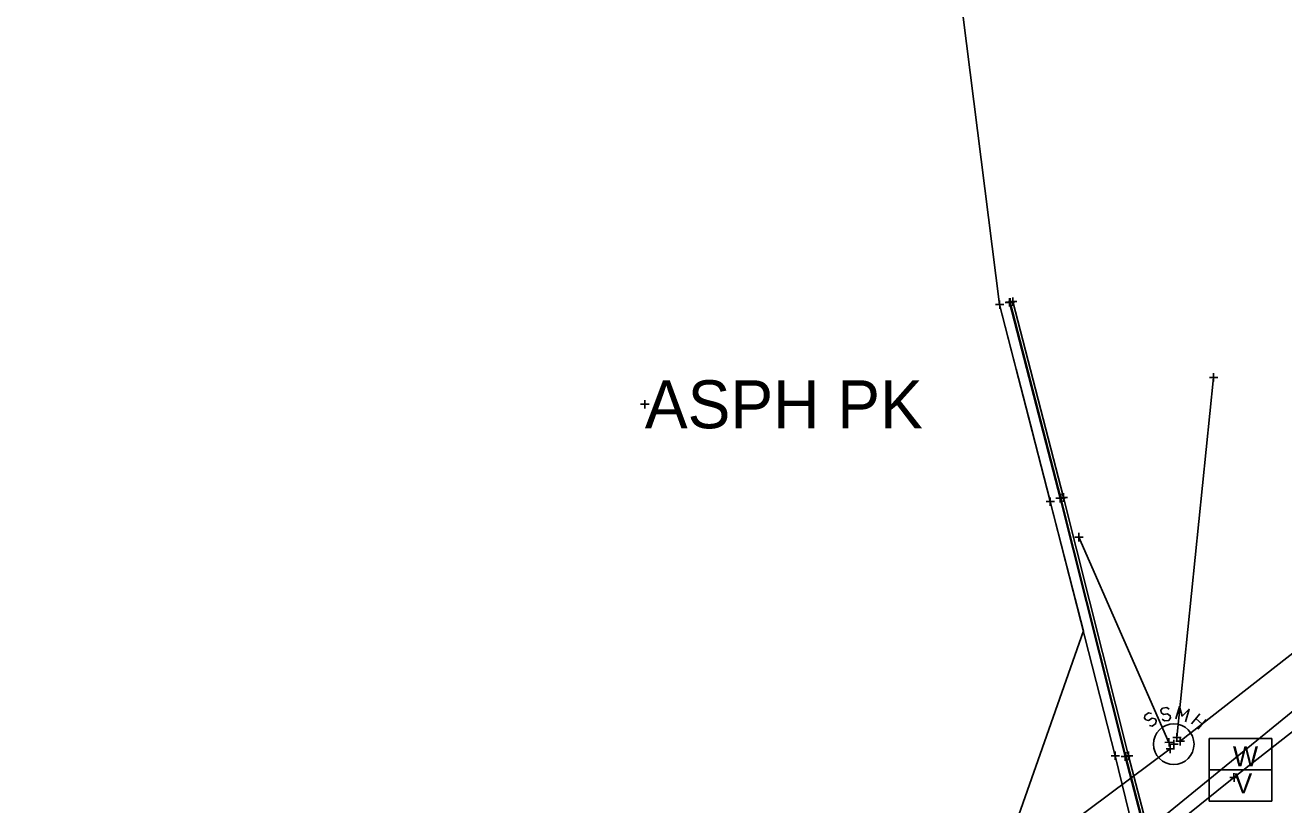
# Model space of a CAD drawing. Extents: x -1 to 1157254, y -1 to 2021979.
# Drawn here: x 1150044.1 to 1150233.1, y 2019619.2 to 2019736.2 of the extents above; entities that cross this region are included whole.
import ezdxf

# ---------------------------------------------------------------- set-up
doc = ezdxf.new("R2010")
doc.units = 0
for name, color, linetype in [('S_BUILDING_ANNOT', 7, 'Continuous'), ('S_CONTOUR_ANNOT', 7, 'Continuous'), ('S_CONTOUR_MINOR', 7, 'Continuous'), ('S_CTL_TABLE', 7, 'Continuous'), ('S_DROP_INLET', 7, 'Continuous'), ('S_EDGE_BITUMINOUS_ANNOT', 7, 'Continuous'), ('S_EDGE_PAVEMENT', 7, 'Continuous'), ('S_EDGE_PAVEMENT_ANNOT', 7, 'Continuous'), ('S_GAS_PUMP_ISLAND_ANNOT', 7, 'Continuous'), ('S_GATE', 7, 'Continuous')]:
    doc.layers.add(name, color=color, linetype=linetype)

msp = doc.modelspace()

# ---------------------------------------------------------------- linework, layer by layer
at = {"layer": 'S_BUILDING_ANNOT'}
for p, q in [((1150190.46, 2019693.61), (1150190.45, 2019694.88)), ((1150191.39, 2019694.6), (1150192.67, 2019694.6)), ((1150191.78, 2019694.7), (1150193.05, 2019694.7)), ((1150192.03, 2019693.96), (1150192.03, 2019695.23)), ((1150192.03, 2019694.6), (1150192.03, 2019694.6)), ((1150192.42, 2019694.06), (1150192.42, 2019695.33)), ((1150192.42, 2019694.7), (1150192.42, 2019694.7)), ((1150189.82, 2019694.25), (1150191.09, 2019694.25)), ((1150190.45, 2019694.25), (1150190.45, 2019694.25)), ((1150221.95, 2019683.31), (1150223.22, 2019683.32)), ((1150222.59, 2019682.68), (1150222.58, 2019683.95)), ((1150222.58, 2019683.32), (1150222.58, 2019683.32)), ((1150137.17, 2019678.65), (1150137.17, 2019679.92)), ((1150136.53, 2019679.28), (1150137.81, 2019679.29)), ((1150137.17, 2019679.28), (1150137.17, 2019679.28)), ((1150197.43, 2019664.67), (1150198.7, 2019664.68)), ((1150198.06, 2019664.04), (1150198.06, 2019665.31)), ((1150198.06, 2019664.67), (1150198.06, 2019664.67)), ((1150199, 2019665.2), (1150200.27, 2019665.2)), ((1150199.39, 2019665.3), (1150200.66, 2019665.3)), ((1150199.64, 2019664.57), (1150199.63, 2019665.84)), ((1150199.64, 2019665.2), (1150199.64, 2019665.2)), ((1150200.03, 2019664.66), (1150200.02, 2019665.94)), ((1150200.02, 2019665.3), (1150200.02, 2019665.3)), ((1150201.72, 2019659.34), (1150203, 2019659.35)), ((1150202.36, 2019658.71), (1150202.36, 2019659.98)), ((1150202.36, 2019659.34), (1150202.36, 2019659.34)), ((1150215.25, 2019628.54), (1150216.52, 2019628.55)), ((1150215.25, 2019628.54), (1150216.52, 2019628.55)), ((1150215.89, 2019627.91), (1150215.88, 2019629.18)), ((1150215.89, 2019627.91), (1150215.88, 2019629.18)), ((1150215.88, 2019628.54), (1150215.88, 2019628.54)), ((1150215.88, 2019628.54), (1150215.88, 2019628.54)), ((1150216.45, 2019629.26), (1150217.72, 2019629.26)), ((1150216.45, 2019629.26), (1150217.72, 2019629.26)), ((1150216.6, 2019627.63), (1150216.6, 2019628.91)), ((1150216.92, 2019628.73), (1150218.19, 2019628.73)), ((1150216.92, 2019628.73), (1150218.19, 2019628.73)), ((1150217.08, 2019628.63), (1150217.08, 2019629.9)), ((1150217.08, 2019628.63), (1150217.08, 2019629.9)), ((1150217.08, 2019629.26), (1150217.08, 2019629.26)), ((1150217.08, 2019629.26), (1150217.08, 2019629.26)), ((1150217.55, 2019628.09), (1150217.55, 2019629.37)), ((1150217.55, 2019628.09), (1150217.55, 2019629.37)), ((1150217.55, 2019628.73), (1150217.55, 2019628.73)), ((1150217.55, 2019628.73), (1150217.55, 2019628.73)), ((1150207.18, 2019626.53), (1150208.46, 2019626.54)), ((1150207.82, 2019625.9), (1150207.82, 2019627.17)), ((1150207.82, 2019626.54), (1150207.82, 2019626.54)), ((1150209.42, 2019625.79), (1150209.42, 2019627.06)), ((1150209.81, 2019625.89), (1150209.8, 2019627.16)), ((1150215.45, 2019627.58), (1150216.72, 2019627.58)), ((1150215.45, 2019627.58), (1150216.72, 2019627.58)), ((1150215.96, 2019628.27), (1150217.24, 2019628.27)), ((1150216.08, 2019626.94), (1150216.08, 2019628.22)), ((1150216.08, 2019626.94), (1150216.08, 2019628.22)), ((1150216.08, 2019627.58), (1150216.08, 2019627.58)), ((1150216.08, 2019627.58), (1150216.08, 2019627.58)), ((1150216.6, 2019628.27), (1150216.6, 2019628.27)), ((1150208.78, 2019626.42), (1150210.05, 2019626.43)), ((1150209.17, 2019626.52), (1150210.44, 2019626.53)), ((1150209.42, 2019626.42), (1150209.42, 2019626.42)), ((1150209.81, 2019626.52), (1150209.81, 2019626.52)), ((1150225.01, 2019623.26), (1150226.28, 2019623.27)), ((1150225.65, 2019622.63), (1150225.64, 2019623.9)), ((1150225.64, 2019623.26), (1150225.64, 2019623.26))]:
    msp.add_line(p, q, dxfattribs=at)
at = {"layer": 'S_CONTOUR_ANNOT'}
for p, q in [((1150221.93, 2019629.11), (1150231.34, 2019629.11)), ((1150221.93, 2019619.7), (1150221.93, 2019629.11)), ((1150231.34, 2019629.11), (1150231.34, 2019619.7)), ((1150221.93, 2019624.42), (1150231.34, 2019624.42)), ((1150231.34, 2019619.7), (1150221.93, 2019619.7))]:
    msp.add_line(p, q, dxfattribs=at)
msp.add_lwpolyline([(1150776.08, 2020000.06), (1150711.77, 2019956.26), (1150627.27, 2019900.66), (1150578.77, 2019864.96), (1150479.12, 2019798.68), (1150423.47, 2019764.16), (1150358.5, 2019722.73), (1150313.96, 2019690.01), (1150273.95, 2019661.03), (1150225.64, 2019623.26), (1150033.5, 2019468.9), (1149971.69, 2019423.78), (1149931.59, 2019393.98), (1149688.42, 2019230.92)], dxfattribs=at)
at = {"layer": 'S_CONTOUR_MINOR'}
for p, q in [((1150212.27, 2019632.57), (1150212.2, 2019632.18)), ((1150212.82, 2019632.96), (1150212.27, 2019632.57)), ((1150213.24, 2019632.88), (1150212.82, 2019632.96)), ((1150219.25, 2019631.33), (1150220.49, 2019632.8)), ((1150212.2, 2019632.18), (1150212.39, 2019631.91)), ((1150212.39, 2019631.91), (1150212.82, 2019631.8)), ((1150212.82, 2019631.8), (1150213.36, 2019632.15)), ((1150213.36, 2019630.98), (1150212.97, 2019631.06)), ((1150213.36, 2019632.15), (1150213.82, 2019632.07)), ((1150213.9, 2019631.37), (1150213.36, 2019630.98)), ((1150213.82, 2019632.07), (1150213.98, 2019631.8)), ((1150213.98, 2019631.8), (1150213.9, 2019631.37)), ((1150219.91, 2019632.11), (1150220.87, 2019631.29)), ((1150221.45, 2019631.99), (1150220.22, 2019630.52))]:
    msp.add_line(p, q, dxfattribs=at)
for points in [[(1150328.79, 2019715.56), (1150217.55, 2019628.73)], [(1150217.08, 2019629.26), (1150222.58, 2019683.32)], [(1150215.88, 2019628.54), (1150202.36, 2019659.34)], [(1150215.92, 2019633.5), (1150215.57, 2019633.77), (1150214.91, 2019633.69), (1150214.68, 2019633.35), (1150214.72, 2019633.04), (1150215.06, 2019632.73), (1150215.68, 2019632.84), (1150216.07, 2019632.53), (1150216.11, 2019632.22), (1150215.84, 2019631.84), (1150215.22, 2019631.76), (1150214.87, 2019632.03)], [(1150218.36, 2019631.64), (1150218.9, 2019633.5), (1150217.85, 2019632.49), (1150217.47, 2019633.93), (1150216.92, 2019632.07)], [(1150216.08, 2019627.58), (1149895.48, 2019388.62)]]:
    msp.add_lwpolyline(points, dxfattribs=at)
msp.add_circle((1150216.6, 2019628.27), 3.05, dxfattribs=at)
at = {"layer": 'S_CTL_TABLE'}
for p, q in [((1150191.94, 2019693.94), (1150191.93, 2019695.21)), ((1150191.3, 2019694.57), (1150192.57, 2019694.57)), ((1150191.93, 2019694.57), (1150191.93, 2019694.57)), ((1150198.9, 2019665.17), (1150200.18, 2019665.18)), ((1150199.54, 2019664.54), (1150199.54, 2019665.81)), ((1150199.54, 2019665.18), (1150199.54, 2019665.18)), ((1150209.32, 2019625.76), (1150209.32, 2019627.04)), ((1150208.68, 2019626.4), (1150209.96, 2019626.4)), ((1150209.32, 2019626.4), (1150209.32, 2019626.4))]:
    msp.add_line(p, q, dxfattribs=at)
at = {"layer": 'S_DROP_INLET'}
msp.add_lwpolyline([(1150343.79, 2019722.31), (1149825.67, 2019300.1)], dxfattribs=at)
at = {"layer": 'S_EDGE_BITUMINOUS_ANNOT'}
msp.add_lwpolyline([(1150191.93, 2019694.57), (1150199.54, 2019665.18), (1150209.32, 2019626.4), (1150213.93, 2019608.7), (1150188.93, 2019602.11), (1150183.89, 2019598.54), (1150182.56, 2019596.28), (1150182.13, 2019596.04), (1150180.28, 2019595.06), (1150179.49, 2019594.62), (1150178.78, 2019593.95), (1150178.26, 2019592.65), (1150178.56, 2019591.42), (1150179.19, 2019589.33), (1150182.45, 2019583.42), (1150187.03, 2019575.29), (1150166.45, 2019569.72), (1150135.63, 2019561.88), (1150107.22, 2019554.65)], dxfattribs=at)
at = {"layer": 'S_EDGE_PAVEMENT'}
for points in [[(1150192.03, 2019694.6), (1150199.64, 2019665.2), (1150209.42, 2019626.42), (1150214.05, 2019608.62), (1150188.97, 2019602.02), (1150183.97, 2019598.47), (1150182.63, 2019596.21), (1150182.17, 2019595.95), (1150180.32, 2019594.97), (1150179.55, 2019594.53), (1150178.86, 2019593.9), (1150178.36, 2019592.65), (1150178.66, 2019591.45), (1150179.28, 2019589.37), (1150182.54, 2019583.46), (1150187.18, 2019575.23), (1150166.47, 2019569.63), (1150135.65, 2019561.78), (1150107.24, 2019554.55)], [(1150192.42, 2019694.7), (1150200.02, 2019665.3), (1150209.81, 2019626.52), (1150214.54, 2019608.34), (1150189.14, 2019601.65), (1150184.27, 2019598.19), (1150182.92, 2019595.91), (1150182.37, 2019595.6), (1150180.52, 2019594.62), (1150179.79, 2019594.21), (1150179.2, 2019593.66), (1150178.78, 2019592.62), (1150179.05, 2019591.55), (1150179.65, 2019589.53), (1150182.89, 2019583.66), (1150187.78, 2019574.98), (1150166.58, 2019569.24), (1150135.75, 2019561.4), (1150107.34, 2019554.17)]]:
    msp.add_lwpolyline(points, dxfattribs=at)
at = {"layer": 'S_EDGE_PAVEMENT_ANNOT'}
msp.add_lwpolyline([(1150190.45, 2019694.25), (1150198.06, 2019664.67), (1150207.82, 2019626.54), (1150211.91, 2019609.69)], dxfattribs=at)
at = {"layer": 'S_GAS_PUMP_ISLAND_ANNOT'}
msp.add_lwpolyline([(1150184.92, 2019737.79), (1150190.45, 2019694.25), (1150192.95, 2019684.56), (1150195.44, 2019674.88), (1150197.93, 2019665.19), (1150198.06, 2019664.67), (1150200.54, 2019654.99), (1150203.02, 2019645.3), (1150188.44, 2019603.71)], dxfattribs=at)

# ---------------------------------------------------------------- texts
at = {"layer": 'S_CONTOUR_ANNOT'}
for s, p in [('W', (1150225.48, 2019624.95)), ('V', (1150225.71, 2019620.89))]:
    msp.add_text(s, height=3, dxfattribs=at).set_placement(p)
at = {"layer": 'S_GATE'}
msp.add_text('ASPH PK', height=7.2, dxfattribs=at).set_placement((1150137.17, 2019675.68))

doc.saveas('drawing.dxf')
